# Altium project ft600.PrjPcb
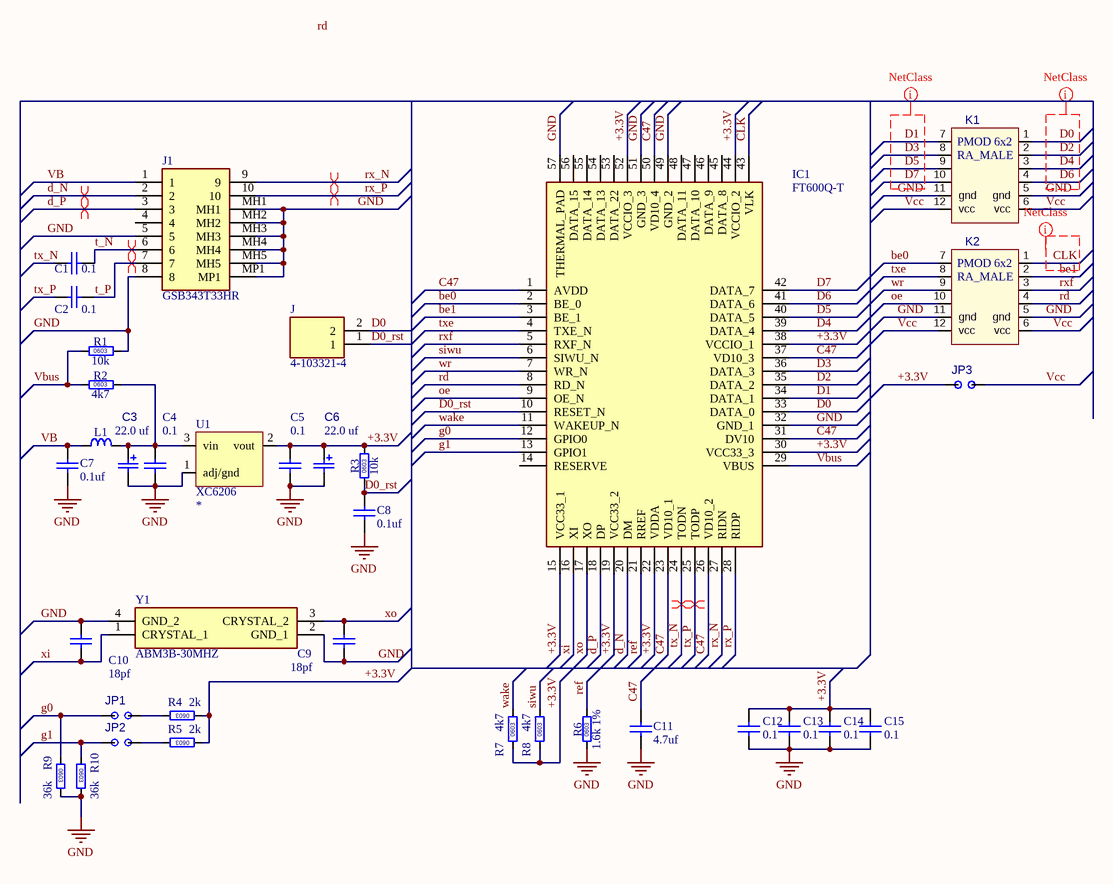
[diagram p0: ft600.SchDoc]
1 sheet, 36 parts. Net scope: global (net labels, ports and power ports of the same name join across sheets).
Board file: ft600.PcbDoc

## Sheet ft600.SchDoc
size A4

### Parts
C1  value 0.1  [SM0402_3D_cap]  (hidden comment: cap0402)
C2  value 0.1  [SM0402_3D_cap]  (hidden comment: cap0402)
C3  CAP_POL_SMA  [CAP_POL_SMA (3216)]  (value not drawn)
C4  value 0.1  [SM0603 _3D_cap]  (hidden comment: cap0603)
C5  value 0.1  [SM0603 _3D_cap]  (hidden comment: cap0603)
C6  CAP_POL_SMA  [CAP_POL_SMA (3216)]  (value not drawn)
C7  value 0.1uf  [SM0603 _3D_cap]  (hidden comment: cap0603)
C8  value 0.1uf  [SM0603 _3D_cap]  (hidden comment: cap0603)
C9  value 18pf  [SM0603 _3D_cap]  (hidden comment: cap0603)
C10  value 18pf  [SM0603 _3D_cap]  (hidden comment: cap0603)
C11  value 4.7uf  [SM0603 _3D_cap]  (hidden comment: cap0603)
C12  value 0.1  [SM0603 _3D_cap]  (hidden comment: cap0603)
C13  value 0.1  [SM0603 _3D_cap]  (hidden comment: cap0603)
C14  value 0.1  [SM0603 _3D_cap]  (hidden comment: cap0603)
C15  value 0.1  [SM0603 _3D_cap]  (hidden comment: cap0603)
IC1  FT600Q-T  [QFN40P700X700X90-57N-D]
J  4-103321-4  [TE_4-103321-4]
J1  GSB343T33HR  [GSB343T33HR]
JP1  JUMPER2  [JUMPER2]  (value not drawn)
JP2  JUMPER2  [JUMPER2]  (value not drawn)
JP3  JUMPER2  [JUMPER2]  (value not drawn)
K1  PMOD_6x2_ra_male  [PMOD_6x2_right_ANGLE]  (value not drawn)
K2  PMOD_6x2_ra_male  [PMOD_6x2_right_ANGLE]  (value not drawn)
L1  75R@100MHz  [SM0603_3D_res]  (value not drawn)
R1  10k  [SM0603_3D_res]
R2  4k7  [SM0603_3D_res]
R3  10k  [SM0603_3D_res]
R4  2k  [SM0603_3D_res]
R5  2k  [SM0603_3D_res]
R6  1.6k 1%  [SM0603_3D_res]
R7  4k7  [SM0603_3D_res]
R8  4k7  [SM0603_3D_res]
R9  36k  [SM0603_3D_res]
R10  36k  [SM0603_3D_res]
U1  XC6206  [SOT-23]
Y1  ABM3B-30MHZ  [ABM3B]

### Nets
GND: C3.2(b) C4.1 C5.1 C6.2(b) C7.1 C8.1 C9.1 C10.2 C11.1 C12.1 C13.1 C14.1 C15.1 IC1.32(GND_1) IC1.49(GND_2) IC1.51(GND_3) IC1.57(THERMAL_PAD) J1.5 J1.8 J1.MH1 J1.MH2 J1.MH3 J1.MH4 J1.MH5 J1.MP1 K1.5(gnd) K1.11(gnd) K2.5(gnd) K2.11(gnd) R1.2 R6.1 R9.2 R10.2 U1.1(adj/gnd) Y1.2(GND_1) Y1.4(GND_2)
+3.3V: C5.2 C6.1(a) C12.2 C13.2 C14.2 C15.2 IC1.15(VCC33_1) IC1.19(VCC33_2) IC1.22(VDDA) IC1.30(VCC33_3) IC1.38(VCCIO_1) IC1.44(VCCIO_2) IC1.52(VCCIO_3) JP3.2 R3.2 R4.1 R5.1 R7.1 R8.1 U1.2(vout)
be0: IC1.2(BE_0) K2.7
be1: IC1.3(BE_1) K2.2
C47: C11.2 IC1.1(AVDD) IC1.23(VD10_1) IC1.26(VD10_2) IC1.31(DV10) IC1.37(VD10_3) IC1.50(VD10_4)
CLK: IC1.43(VLK) K2.1
D0: IC1.33(DATA_0) J.2 K1.1
D0_rst: C8.2 IC1.10(RESET_N) J.1 R3.1
D1: IC1.34(DATA_1) K1.7
D2: IC1.35(DATA_2) K1.2
D3: IC1.36(DATA_3) K1.8
D4: IC1.39(DATA_4) K1.3
D5: IC1.40(DATA_5) K1.9
D6: IC1.41(DATA_6) K1.4
D7: IC1.42(DATA_7) K1.10
d_N: IC1.20(DM) J1.2
d_P: IC1.18(DP) J1.3
g0: IC1.12(GPIO0) JP1.2 R9.1
g1: IC1.13(GPIO1) JP2.2 R10.1
oe: IC1.9(OE_N) K2.10
rd: IC1.8(RD_N) K2.4
ref: IC1.21(RREF) R6.2
rx_N: IC1.27(RIDN) J1.9
rx_P: IC1.28(RIDP) J1.10
rxf: IC1.5(RXF_N) K2.3
siwu: IC1.6(SIWU_N) R8.2
t_N: C1.1 J1.6
t_P: C2.1 J1.7
tx_N: C1.2 IC1.24(TODN)
tx_P: C2.2 IC1.25(TODP)
txe: IC1.4(TXE_N) K2.8
VB: C7.2 J1.1 L1.1
Vbus: IC1.29(VBUS) R1.1 R2.1
Vcc: JP3.1 K1.6(vcc) K1.12(vcc) K2.6(vcc) K2.12(vcc)
wake: IC1.11(WAKEUP_N) R7.2
wr: IC1.7(WR_N) K2.9
xi: C10.1 IC1.16(XI) Y1.1(CRYSTAL_1)
xo: C9.2 IC1.17(XO) Y1.3(CRYSTAL_2)
NetC3_1: C3.1(a) C4.2 L1.2 R2.2 U1.3(vin)
NetJP1_1: JP1.1 R4.2
NetJP2_1: JP2.1 R5.2

Not connected (* = marked no-connect by the designer): IC1 14(RESERVE) 45(DATA_8) 46(DATA_9) 47(DATA_10) 48(DATA_11) 53(DATA_22) 54(DATA_13) 55(DATA_14) 56(DATA_15); J1 4

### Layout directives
differential pair: d_N, d_P, rx_N, rx_P, t_N, t_P, tx_N, tx_P
net class data: CLK, D0, D1, D2, D3, D4, D5, D6, D7

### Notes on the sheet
- Labels drawn without touching a wire or pin: rd

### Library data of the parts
C1 C2 = cap0402: Capacitor  0402 inch
C3 C6 = CAP_POL_SMA: CAP_POL_SMA(3216)
C4 C5 C7-C15 = cap0603: Capacitor  0603 inch
IC1 = FT600Q-T: Integrated Circuit; Manufacturer_Name: FTDI Chip
J = 4-103321-4: Conn Unshrouded Header HDR 2 POS 2.54mm Solder ST Thru-Hole Carton; MF: TE Connectivity
J1 = GSB343T33HR: Connector; Manufacturer_Name: Amphenol
K1 K2 = PMOD_6x2_ra_male: PMOD_6x2_right_angle
L1 = chip inductance 0603: Part Number: IND0805_MURATA_BLM21BB750SN1D; Part Description: SMD EMIFIL Suppression Chip Ferrite Bead; Manufacturer: MURATA; Manufacturer Part Number: BLM21BB750SN1D; Power: 700mA; Resistance: 0.16R; Tolerance: ±25%; Table: Inductors SMD
R1 R3-R5 R9 R10 = Res_0603_EU: Part Number: R1206_4K7_1%_0.25W_100PPM; Part Description: General Purpose Thick Film Chip Resistor; Manufacturer: GENERIC; Manufacturer1 Part Number: NRC12F4701TRF; Value: 4k7; Power: 0.25W; TC: ±100ppm/°C; Tolerance: ±1%; Table: Resistors SMD
R2 R7 R8 = Res_0603_EU: Part Number: R1206_4K7_1%_0.25W_100PPM; Part Description: General Purpose Thick Film Chip Resistor; Manufacturer: GENERIC; Manufacturer1 Part Number: NRC12F4701TRF; Power: 0.25W; TC: ±100ppm/°C; Tolerance: ±1%; Table: Resistors SMD
R6 = Res_0603_EU: Part Number: R1206_4K7_1%_0.25W_100PPM; Part Description: General Purpose Thick Film Chip Resistor; Manufacturer: GENERIC; Manufacturer1 Part Number: NRC12F4701TRF; Value: 4k7; Power: 0.25W; TC: ±100ppm/°C; Table: Resistors SMD
U1 = XC6206: SOT-23-3 ldo
Y1 = ABM3B-11.0592MHZ-10-1-U-T: Crystal or Oscillator; Manufacturer_Name: ABRACON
